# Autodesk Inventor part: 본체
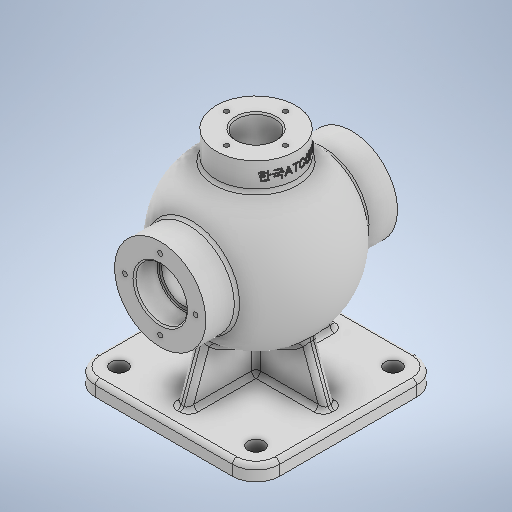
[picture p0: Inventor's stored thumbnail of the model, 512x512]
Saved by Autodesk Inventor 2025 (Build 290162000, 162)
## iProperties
Created: 2024-07
Part Number: 본체
Material: 일반
Document SubType Name: Modeling
Designer: anfro
Density: 1 g/cm^3
Appearance: 기본값
Author: anfro
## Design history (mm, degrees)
sketch "스케치1"
  geometry: L1 (62.5, 62.5)-(-62.5, 62.5); L2 (-62.5, 62.5)-(-62.5, -62.5); L3 (-62.5, -62.5)-(62.5, -62.5); L4 (62.5, -62.5)-(62.5, 62.5); L5 (62.5, 62.5)-(-62.5, -62.5); L6 (-62.5, 62.5)-(62.5, -62.5); 1 further point
  constraints: 12 end point, 2 midpoint, 2 parallel, 1 horizontal, 1 perpendicular
  dimensions: "d0" = 125 distance of L3.end L2.end; "d1" = 125 distance of L2.end L1.end
extrude "돌출1" new body sketch "스케치1" distance "d2" = 10; taper "d3" = 0 deg
node "작업 평면1"
sketch "스케치2" dims "d5" = 108, "d6" = 88
  geometry: L1 (-31, 65)-(31, 65); L2 (31, 65)-(31, 44.215); L3 (31, 44.215)-(-31, 44.215); L4 (-31, 44.215)-(-31, 65); L5 (-31, 65)-(31, 44.215); L6 (31, 65)-(-31, 44.215); L7 (0, 0)-(0, -131.339); L8 (-17.5, 65)-(17.5, 65); L9 (17.5, 65)-(17.5, 49); L10 (17.5, 49)-(-17.5, 49); L11 (-17.5, 49)-(-17.5, 65); L12 (-17.5, 65)-(17.5, 49); L13 (17.5, 65)-(-17.5, 49); L14 (0, 0)-(87.598, 0); L15 (31, -65)-(31, -44.215); L16 (17.5, -65)-(17.5, -49); L17 (17.5, -49)-(-17.5, -49); L18 (-17.5, -49)-(-17.5, -65); L19 (-17.5, -65)-(17.5, -65); L20 (-17.5, -65)-(17.5, -49); L21 (17.5, -65)-(-17.5, -49); L22 (31, -44.215)-(-31, -44.215); L23 (-31, -44.215)-(-31, -65); L24 (-31, -65)-(31, -44.215); L25 (31, -65)-(-31, -44.215); L26 (-31, -65)-(31, -65); L27 (15, 49)-(-15, 49); L28 (-15, 49)-(-15, 41.364); L29 (-15, 41.364)-(15, 41.364); L30 (15, 41.364)-(15, 49); L31 (-15, -49)-(-15, -41.364); L32 (15, -41.364)-(15, -49); L33 (-15, -41.364)-(15, -41.364); L34 (15, -49)-(-15, -49); 19 further points
  constraints: 68 end point, 14 symmetric about line, 6 parallel, 4 horizontal, 4 midpoint, 3 perpendicular, 2 coincident, 1 collinear, 1 point on line, 1 vertical, 1 vertical alignment, 8 other
  dimensions: "d7" = 62 distance of L1.start L1.end; "d8" = 65 distance from line of point (0, 0) L1; "d9" = 35 distance of L9.end L10.end; "d10" = 16 distance of L8.end L9.end; "d11" = 30 distance of L28.end L29.end
revolve "회전1" sketch "스케치2" stored, may be unused: angle "d12" = 90 deg
sketch "스케치4"
  geometry: L1 (-50.5, 4)-(50.5, 4); L2 (50.5, 4)-(50.5, -4); L3 (50.5, -4)-(-50.5, -4); L4 (-50.5, -4)-(-50.5, 4); L5 (-50.5, 4)-(50.5, -4); L6 (50.5, 4)-(-50.5, -4); L7 (-4, -50.5)-(4, -50.5); L8 (4, -50.5)-(4, 50.5); L9 (4, 50.5)-(-4, 50.5); L10 (-4, 50.5)-(-4, -50.5); L11 (-4, -50.5)-(4, 50.5); L12 (4, -50.5)-(-4, 50.5); L13 (62.5, -62.5)-(62.5, 62.5) reference; L14 (62.5, 62.5)-(-62.5, 62.5) reference; L15 (-62.5, 62.5)-(-62.5, -62.5) reference; L16 (-62.5, -62.5)-(62.5, -62.5) reference; 5 further points
  constraints: 24 end point, 4 midpoint, 4 parallel, 2 horizontal, 2 perpendicular
  dimensions: "d19" = 8 distance of L1.end L2.end; "d20" = 8 distance of L9.end L8.end; "d67" = 12 distance between parallel lines of L15 L4; "d70" = 12 distance between parallel lines of L16 L7
extrude "돌출3" join sketch "스케치4" stored distance "d23" = 10; taper "d24" = 0 deg
feature "면 기울기1" dims angle "d25" = 20 deg
sketch "스케치5"
  geometry: 1 further point
fillet "모깎기1" dims "d26" = 16
sketch "스케치6"
  geometry: C1 r 5.5 at (-46.5, 46.5); C2 r 5.5 at (46.5, 46.5); C3 r 5.5 at (46.5, -46.5); C4 r 5.5 at (-46.5, -46.5); A1 r 16 centre (-46.5, 46.5) between (-46.5, 62.5) and (-62.5, 46.5) reference; A2 r 16 centre (46.5, 46.5) between (62.5, 46.5) and (46.5, 62.5) reference; A3 r 16 centre (46.5, -46.5) between (46.5, -62.5) and (62.5, -46.5) reference; A4 r 16 centre (-46.5, -46.5) between (-62.5, -46.5) and (-46.5, -62.5) reference; 1 further point
  constraints: 4 centre point, 4 coincident
  dimensions: "d27" = 11 diameter of C1; "d28" = 11 diameter of C2; "d29" = 11 diameter of C3; "d30" = 11 diameter of C4
extrude "돌출4" cut sketch "스케치6" extent not by distance; stored distance "d31" = 0; taper "d32" = 0 deg
node "작업 평면2"
sketch "스케치7"
  geometry: C1 r 27 at (0, 0); 1 further point
  constraints: 1 centre point, 1 coincident
  dimensions: "d34" = 54 diameter of C1
extrude "돌출5" join sketch "스케치7" stored distance "d35" = 10; taper "d36" = 0 deg
sketch "스케치8"
  geometry: C1 r 13 at (0, 0); 1 further point
  constraints: 1 centre point, 1 coincident
  dimensions: "d37" = 26 diameter of C1
extrude "돌출6" cut sketch "스케치8" stored distance "d38" = 34.5; taper "d39" = 0 deg
chamfer "모따기1" distance "d40" = 1; stored, may be unused: second distance "d41" = 2, angle "d42" = 45 deg
fillet "모깎기2" dims "d43" = 0.6
fillet "모깎기3" dims "d44" = 3
fillet "모깎기4" dims "d45" = 3
fillet "모깎기5" dims "d46" = 3
fillet "모깎기6" dims "d47" = 3
node "작업 평면3"
sketch "스케치9"
  geometry: L1 (-14.44, 0.888)-(-14.44, -0.888); L2 (-14.44, -0.888)-(-3.56, -0.888); L3 (-3.56, -0.888)-(-3.56, 0.888); L4 (-3.56, 0.888)-(-14.44, 0.888); L5 (0, -27)-(0, 27) reference; 3 further points
  constraints: 2 midpoint, 1 horizontal alignment, 2 other
  dimensions: "d48" = 9 distance from line of L5 point (-9, 0.888)
feature "엠보싱1" sketch "스케치9" dims "d0" = 125, "d1" = 125, "d5" = 108, "d6" = 88, "d7" = 62, "d8" = 65, "d9" = 35, "d10" = 16, "d11" = 30, "d49" = 0.5, "d50" = 0
sketch "스케치10"
  geometry: C1 r 31 at (0, 0) reference; A1 r 24 centre (0, 0) between (0, 24) and (24, 0); 3 further points
  constraints: 4 point on circle, 2 horizontal alignment, 2 vertical alignment, 1 centre point, 1 coincident
  dimensions: "d51" = 48 diameter of A1
hole "구멍1" sketch "스케치10" at (0, 24), (24, 0), (0, -24), (-24, 0) diameter "d52" = 3.242; stored, may be unused: countersink angle "d56" = 90 deg, drill point angle "d58" = 118 deg; dims "d53" = 12, "d54" = 4, "d55" = 2, "d57" = 15
sketch "스케치11"
  geometry: A1 r 20 centre (0, 0) between (-20, 0) and (0, 20); 3 further points
  constraints: 4 point on circle, 2 horizontal alignment, 2 vertical alignment, 1 centre point, 1 coincident
  dimensions: "d59" = 40 diameter of A1
hole "구멍2" sketch "스케치11" at (-20, 0), (0, 20), (20, 0), (0, -20) diameter "d60" = 3.242; stored, may be unused: countersink angle "d64" = 90 deg, drill point angle "d66" = 118 deg; dims "d61" = 9, "d62" = 4, "d63" = 2, "d65" = 11
fillet "모깎기7" dims "d68" = 3
feature "Ҋ耀Ҍ耀Ҏ耀Ґ耀Ғ耀Ҕ耀Җ耀Ҙ耀" dims "d0" = 125, "d1" = 125, "d2" = 10, "d3" = 0, "d4" = 85, "d5" = 108, "d6" = 88, "d7" = 62, "d8" = 65, "d9" = 35, "d10" = 16, "d11" = 30, "d12" = 90 deg, "d19" = 8, "d20" = 8, "d23" = 10, "d24" = 0, "d25" = 20 deg, "d26" = 16, "d27" = 11, "d28" = 11, "d29" = 11, "d30" = 11, "d31" = 0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
node "솔리드1"
mirror "미러1"
feature "A9D066F2-1C7D-4E18-AEED-F7BC21143FA4" dims "d52" = 3.242, "d53" = 12, "d54" = 4, "d55" = 2, "d56" = 90 deg, "d57" = 15, "d58" = 118 deg
